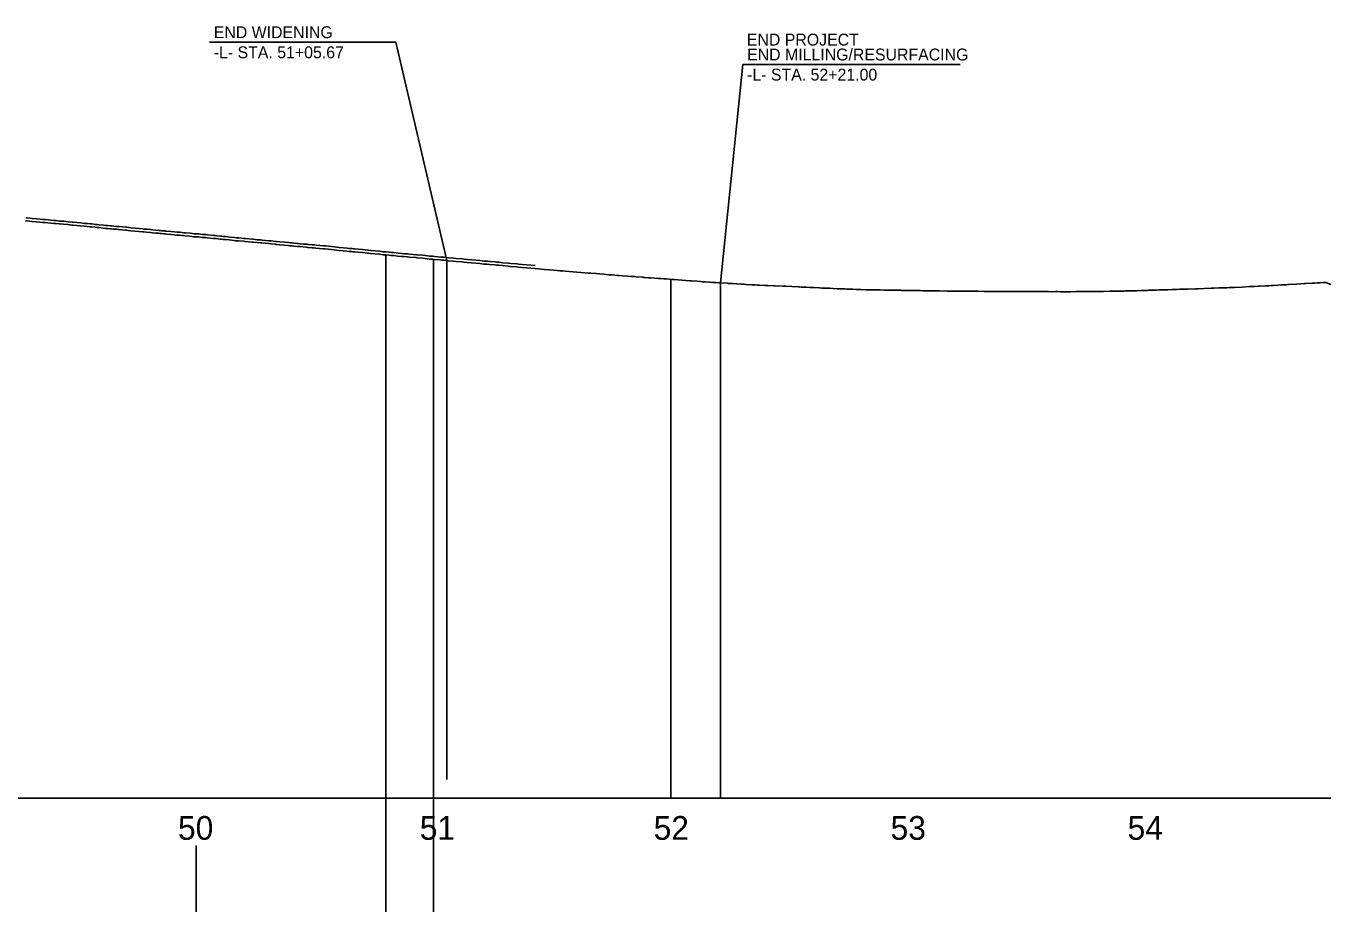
# Model space of a CAD drawing. Extents: x 2115752 to 2121174, y 562881 to 567245.
# Drawn here: x 2120625 to 2121174, y 566328 to 566701 of the extents above; entities that cross this region are included whole.
import ezdxf

# ---------------------------------------------------------------- set-up
doc = ezdxf.new("R2010")
doc.units = 0
for name, color, linetype in [('Exist Profile Cell', 7, 'Continuous'), ('Exist Vertical Profile Ground Line', 7, 'Continuous'), ('Exist Vertical Profile Horizontal Axis Label Major', 7, 'Continuous'), ('Prop VPI Label', 7, 'Continuous'), ('Scratch_Level_1', 7, 'Continuous')]:
    doc.layers.add(name, color=color, linetype=linetype)

msp = doc.modelspace()

# ---------------------------------------------------------------- linework, layer by layer
at = {"layer": 'Exist Profile Cell'}
msp.add_line((2116696.3, 566375.81), (2121174.42, 566375.81), dxfattribs=at)
at = {"layer": 'Exist Vertical Profile Ground Line'}
for points in [[(2120624.5, 566618.97), (2120625.07, 566618.92), (2120626.09, 566618.8), (2120627.11, 566618.72), (2120628.94, 566618.55), (2120630.45, 566618.41), (2120631.56, 566618.27), (2120632.57, 566618.21), (2120633.82, 566618.09), (2120635.04, 566617.95), (2120636.31, 566617.88), (2120636.7, 566617.85), (2120637.16, 566617.81), (2120638.57, 566617.63), (2120640.46, 566617.5), (2120642.26, 566617.34), (2120643.96, 566617.19), (2120644.45, 566617.14), (2120647.64, 566616.84), (2120649.14, 566616.64), (2120650.48, 566616.53), (2120651.62, 566616.44), (2120652.2, 566616.38), (2120653.77, 566616.23), (2120654.57, 566616.13), (2120655.3, 566616.09), (2120657.16, 566615.91), (2120658.08, 566615.79), (2120658.97, 566615.73), (2120659.96, 566615.63), (2120660.52, 566615.58), (2120661.58, 566615.45), (2120662.71, 566615.39), (2120663.3, 566615.33), (2120663.81, 566615.29), (2120666.62, 566615.03), (2120667.16, 566614.98), (2120667.71, 566614.9), (2120668.75, 566614.76), (2120670.55, 566614.64), (2120672.22, 566614.43), (2120673.77, 566614.32), (2120674.36, 566614.26), (2120675.47, 566614.16), (2120677.14, 566614.01), (2120678.01, 566613.93), (2120679.28, 566613.76), (2120680.44, 566613.69), (2120681.12, 566613.62), (2120681.8, 566613.56), (2120682.82, 566613.44), (2120683.22, 566613.41), (2120683.77, 566613.37), (2120685.62, 566613.21), (2120687.04, 566613.08), (2120688.2, 566612.95), (2120689.35, 566612.88), (2120690.35, 566612.78), (2120690.98, 566612.71), (2120691.71, 566612.62), (2120693.7, 566612.49), (2120695.33, 566612.28), (2120697.26, 566612.17)], [(2120697.26, 566612.17), (2120698.82, 566611.97), (2120700.43, 566611.89), (2120700.98, 566611.83), (2120703.66, 566611.56), (2120704.18, 566611.51), (2120704.76, 566611.45), (2120706.48, 566611.28), (2120706.98, 566611.23), (2120707.69, 566611.16), (2120708.62, 566611.05), (2120710.26, 566610.9), (2120712.33, 566610.7), (2120713.05, 566610.59), (2120713.62, 566610.56), (2120714.24, 566610.5), (2120716.31, 566610.32), (2120716.94, 566610.26), (2120719.99, 566610), (2120720.29, 566609.97), (2120721.99, 566609.77), (2120723.49, 566609.67), (2120724.02, 566609.62), (2120726.78, 566609.36), (2120727.75, 566609.26), (2120729.75, 566609.06), (2120730.08, 566609.02), (2120731.52, 566608.88), (2120733.41, 566608.71), (2120735.16, 566608.54), (2120736, 566608.43), (2120736.72, 566608.39), (2120737.5, 566608.32), (2120739.03, 566608.18), (2120740.02, 566608.08), (2120741.41, 566607.94), (2120743.01, 566607.81), (2120743.43, 566607.77), (2120745.25, 566607.6), (2120746.01, 566607.53), (2120746.73, 566607.46), (2120749.87, 566607.2), (2120750.23, 566607.17), (2120750.66, 566607.12), (2120753.23, 566606.83), (2120754.46, 566606.71), (2120756.49, 566606.51), (2120758.24, 566606.34), (2120759.78, 566606.19), (2120760.76, 566606.1), (2120761.96, 566606), (2120762.5, 566605.93), (2120762.99, 566605.89), (2120764.49, 566605.72), (2120766.36, 566605.59), (2120768.52, 566605.38), (2120768.89, 566605.34), (2120769.82, 566605.25), (2120773.53, 566604.9), (2120775.07, 566604.7), (2120776.27, 566604.63), (2120777.58, 566604.51), (2120778.56, 566604.38), (2120779.53, 566604.31), (2120781.32, 566604.14), (2120782.79, 566604), (2120784.03, 566603.87), (2120785.31, 566603.77), (2120786.14, 566603.7), (2120789.01, 566603.46), (2120789.44, 566603.41), (2120791.78, 566603.2), (2120792.78, 566603.11), (2120794.54, 566602.88), (2120795.91, 566602.8), (2120796.78, 566602.71), (2120799.27, 566602.47), (2120799.9, 566602.41), (2120800.65, 566602.35), (2120802.52, 566602.16), (2120804.58, 566601.97), (2120805.84, 566601.86), (2120808.34, 566601.67), (2120809.1, 566601.6), (2120810.52, 566601.42), (2120812.38, 566601.3), (2120815.9, 566600.97), (2120817.58, 566600.77), (2120818.93, 566600.67), (2120820.07, 566600.56), (2120822.16, 566600.37), (2120822.91, 566600.3), (2120823.87, 566600.23), (2120825.47, 566600.08), (2120827.75, 566599.88), (2120828.76, 566599.79), (2120831.37, 566599.55), (2120832.04, 566599.49), (2120833.58, 566599.33), (2120835.5, 566599.2), (2120839.1, 566598.88)], [(2120839.1, 566598.88), (2120840.75, 566598.7), (2120841.83, 566598.63), (2120843.1, 566598.52), (2120845.16, 566598.33), (2120847.02, 566598.17), (2120848.41, 566598.06), (2120849.51, 566597.94), (2120850.89, 566597.86), (2120851.78, 566597.78), (2120855.04, 566597.42), (2120858.41, 566597.23), (2120860.12, 566597.08), (2120861.51, 566596.98), (2120862.01, 566596.94), (2120862.55, 566596.89), (2120864.84, 566596.72), (2120866.26, 566596.6), (2120868.15, 566596.44), (2120869.12, 566596.36), (2120870.26, 566596.26), (2120871.4, 566596.16), (2120873.93, 566595.95), (2120874.66, 566595.89), (2120876.08, 566595.78), (2120878, 566595.62), (2120879.66, 566595.53), (2120881.21, 566595.45), (2120881.67, 566595.41), (2120884.53, 566595.19), (2120884.96, 566595.16), (2120885.57, 566595.11), (2120886.87, 566595), (2120887.75, 566594.94), (2120889.42, 566594.82), (2120891.05, 566594.72), (2120892.06, 566594.67), (2120893.33, 566594.56), (2120894.37, 566594.49), (2120896.98, 566594.31), (2120897.67, 566594.26), (2120899.23, 566594.14), (2120900.99, 566593.96), (2120902.64, 566593.85), (2120904.13, 566593.74), (2120904.55, 566593.71), (2120905.02, 566593.67), (2120907.46, 566593.5), (2120908.79, 566593.4), (2120909.81, 566593.31), (2120910.72, 566593.27), (2120912.65, 566593.13), (2120914.02, 566593.04), (2120915.16, 566592.98), (2120916.56, 566592.88), (2120916.95, 566592.85), (2120917.29, 566592.83), (2120920.19, 566592.64), (2120920.64, 566592.61), (2120922.27, 566592.5), (2120924.1, 566592.4), (2120925.79, 566592.3), (2120927.24, 566592.24), (2120928.1, 566592.2), (2120930.4, 566592.07), (2120931.1, 566592.05), (2120931.9, 566591.98), (2120932.9, 566591.9), (2120933.74, 566591.88), (2120935.92, 566591.78), (2120936.5, 566591.74), (2120937.02, 566591.72), (2120939.65, 566591.59), (2120940.3, 566591.56), (2120943.63, 566591.43), (2120944.61, 566591.4), (2120947.31, 566591.33), (2120950.17, 566591.14), (2120950.6, 566591.09), (2120951.17, 566591.06), (2120953.41, 566590.96), (2120955.02, 566590.89), (2120956.74, 566590.81), (2120958.9, 566590.69), (2120959.9, 566590.62), (2120961.2, 566590.55), (2120962.77, 566590.55), (2120963.26, 566590.53), (2120964.75, 566590.43), (2120966.57, 566590.32), (2120968.37, 566590.28), (2120969.82, 566590.26), (2120970.52, 566590.24), (2120971.87, 566590.17), (2120973.07, 566590.15), (2120974.42, 566590.1), (2120976.37, 566590.03), (2120978.3, 566589.96), (2120979.67, 566589.92), (2120982.08, 566589.86), (2120982.89, 566589.84)], [(2120982.89, 566589.84), (2120984.3, 566589.83), (2120986.26, 566589.82), (2120987.99, 566589.8), (2120989.85, 566589.77), (2120992.79, 566589.7), (2120993.17, 566589.69), (2120993.61, 566589.68), (2120994.97, 566589.62), (2120996.08, 566589.65), (2120997.61, 566589.62), (2120999.33, 566589.59), (2121001.36, 566589.57), (2121002.58, 566589.52), (2121005.2, 566589.52), (2121005.93, 566589.5), (2121009.4, 566589.46), (2121012.88, 566589.39), (2121014.42, 566589.33), (2121015.7, 566589.34), (2121016.95, 566589.32), (2121018.92, 566589.27), (2121020.77, 566589.27), (2121022.32, 566589.27), (2121024.59, 566589.29), (2121025.53, 566589.29), (2121028.36, 566589.25), (2121028.79, 566589.24), (2121030.41, 566589.17), (2121032.06, 566589.21), (2121032.38, 566589.21), (2121035.36, 566589.2), (2121036.19, 566589.2), (2121038.68, 566589.17), (2121039.32, 566589.15), (2121040.02, 566589.16), (2121041.95, 566589.16), (2121042.81, 566589.14), (2121043.81, 566589.16), (2121044.57, 566589.15), (2121045.22, 566589.15), (2121047.79, 566589.16), (2121048.15, 566589.16), (2121048.5, 566589.16), (2121051.91, 566589.16), (2121055.14, 566589.16), (2121055.51, 566589.16), (2121056.97, 566589.12), (2121058.36, 566589.13), (2121059.37, 566589.13), (2121060.52, 566589.1), (2121061.58, 566589.12), (2121063.21, 566589.12), (2121064.91, 566589.12), (2121067.1, 566589.15), (2121068.22, 566589.15), (2121070.96, 566589.18), (2121071.51, 566589.18), (2121074.77, 566589.23), (2121078.02, 566589.25), (2121078.57, 566589.26), (2121081.29, 566589.3), (2121082.45, 566589.33), (2121084.57, 566589.37), (2121085.38, 566589.37), (2121086.39, 566589.4), (2121087.21, 566589.4), (2121087.9, 566589.43), (2121090.18, 566589.48), (2121091.2, 566589.5), (2121092.57, 566589.53), (2121094.46, 566589.6), (2121097.01, 566589.68), (2121097.75, 566589.71), (2121099.56, 566589.74), (2121100.94, 566589.81), (2121101.86, 566589.84), (2121104.2, 566589.91), (2121105.65, 566589.95), (2121107.52, 566590), (2121108.43, 566590.02), (2121109.54, 566590.08), (2121110.8, 566590.11), (2121111.95, 566590.11), (2121113.44, 566590.19), (2121114.08, 566590.21), (2121117.36, 566590.32), (2121118.49, 566590.36), (2121121.04, 566590.44), (2121123.99, 566590.54), (2121124.43, 566590.55), (2121124.92, 566590.58), (2121127.19, 566590.67), (2121127.92, 566590.69), (2121128.75, 566590.73), (2121130.51, 566590.8), (2121131.51, 566590.83), (2121132.7, 566590.89), (2121133.31, 566590.9), (2121133.85, 566590.93), (2121137.04, 566591.07)], [(2121137.04, 566591.07), (2121140.03, 566591.23), (2121140.43, 566591.25), (2121142.12, 566591.29), (2121143.94, 566591.42), (2121144.29, 566591.44), (2121146.88, 566591.58), (2121147.45, 566591.61), (2121148.12, 566591.65), (2121149.26, 566591.68), (2121150.18, 566591.75), (2121152.03, 566591.86), (2121153.45, 566591.94), (2121155.77, 566592.07), (2121156.31, 566592.09), (2121156.76, 566592.13), (2121159.99, 566592.32), (2121161.6, 566592.38), (2121163.25, 566592.51), (2121163.67, 566592.53), (2121166.59, 566592.71), (2121167.51, 566592.77), (2121168.77, 566592.81), (2121169.79, 566592.89), (2121171.3, 566592.98), (2121172.29, 566593), (2121172.63, 566592.81), (2121174.42, 566592.08)]]:
    msp.add_lwpolyline(points, dxfattribs=at)
at = {"layer": 'Prop VPI Label'}
for p, q in [((2120701.97, 566694.12), (2120780.53, 566694.12)), ((2120801.97, 566602.21), (2120780.53, 566694.12)), ((2120917.3, 566592.83), (2120926.69, 566684.74)), ((2120926.69, 566684.74), (2121018.26, 566684.74))]:
    msp.add_line(p, q, dxfattribs=at)
at = {"layer": 'Scratch_Level_1'}
for p, q in [((2120776.3, 566327.95), (2120776.3, 566604.62)), ((2120796.3, 566327.95), (2120796.3, 566602.79)), ((2120801.97, 566383.73), (2120801.97, 566602.21)), ((2120896.3, 566375.81), (2120896.3, 566594.29)), ((2120917.3, 566375.81), (2120917.3, 566592.83)), ((2120696.3, 566327.95), (2120696.3, 566355.91))]:
    msp.add_line(p, q, dxfattribs=at)
for points in [[(2120624.61, 566620.21), (2120625.2, 566620.17), (2120626.21, 566620.04), (2120627.21, 566619.96), (2120629.06, 566619.8), (2120630.58, 566619.65), (2120631.67, 566619.52), (2120632.67, 566619.46), (2120633.96, 566619.33), (2120635.14, 566619.19), (2120636.4, 566619.13), (2120636.81, 566619.09), (2120637.29, 566619.05), (2120638.69, 566618.87), (2120640.55, 566618.75), (2120642.37, 566618.59), (2120644.07, 566618.43), (2120644.57, 566618.39), (2120647.78, 566618.08), (2120649.27, 566617.88), (2120650.58, 566617.78), (2120651.73, 566617.68), (2120652.32, 566617.63), (2120653.91, 566617.47), (2120654.68, 566617.37), (2120655.39, 566617.33), (2120657.3, 566617.15), (2120658.2, 566617.04), (2120659.07, 566616.98), (2120660.08, 566616.88), (2120660.66, 566616.82), (2120661.69, 566616.7), (2120662.8, 566616.63), (2120663.42, 566616.58), (2120663.92, 566616.53), (2120666.74, 566616.27), (2120667.31, 566616.22), (2120667.88, 566616.14), (2120668.88, 566616), (2120670.68, 566615.89), (2120672.35, 566615.67), (2120673.88, 566615.57), (2120674.48, 566615.51), (2120675.58, 566615.41), (2120677.26, 566615.25), (2120678.15, 566615.17), (2120679.4, 566615.01), (2120680.54, 566614.94), (2120681.23, 566614.86), (2120681.92, 566614.81), (2120682.94, 566614.68), (2120683.3, 566614.66), (2120683.86, 566614.62), (2120685.73, 566614.46), (2120687.17, 566614.33), (2120688.3, 566614.2), (2120689.45, 566614.13), (2120690.48, 566614.03), (2120691.13, 566613.95), (2120691.82, 566613.86), (2120693.82, 566613.74), (2120695.45, 566613.53), (2120697.33, 566613.42)], [(2120697.43, 566613.41), (2120698.93, 566613.22), (2120700.52, 566613.13), (2120701.1, 566613.08), (2120703.78, 566612.8), (2120704.31, 566612.75), (2120704.89, 566612.69), (2120706.61, 566612.52), (2120707.1, 566612.47), (2120707.82, 566612.4), (2120708.75, 566612.3), (2120710.38, 566612.14), (2120712.48, 566611.94), (2120713.18, 566611.84), (2120713.72, 566611.8), (2120714.35, 566611.75), (2120716.42, 566611.56), (2120717.05, 566611.5), (2120720.1, 566611.24), (2120720.42, 566611.21), (2120722.1, 566611.02), (2120723.59, 566610.92), (2120724.14, 566610.87), (2120726.9, 566610.6), (2120727.87, 566610.5), (2120729.87, 566610.3), (2120730.2, 566610.27), (2120731.64, 566610.13), (2120733.52, 566609.95), (2120735.3, 566609.79), (2120736.12, 566609.67), (2120736.81, 566609.63), (2120737.61, 566609.56), (2120739.15, 566609.42), (2120740.15, 566609.32), (2120741.52, 566609.18), (2120743.13, 566609.06), (2120743.55, 566609.01), (2120745.37, 566608.85), (2120746.13, 566608.78), (2120746.84, 566608.71), (2120749.97, 566608.45), (2120750.35, 566608.42), (2120750.8, 566608.36), (2120753.36, 566608.08), (2120754.59, 566607.96), (2120756.61, 566607.75), (2120758.36, 566607.59), (2120759.9, 566607.44), (2120760.87, 566607.35), (2120762.09, 566607.24), (2120762.62, 566607.17), (2120763.11, 566607.14), (2120764.6, 566606.97), (2120766.47, 566606.83), (2120768.64, 566606.62), (2120769.01, 566606.59), (2120769.94, 566606.49), (2120773.67, 566606.15), (2120775.19, 566605.94), (2120776.37, 566605.87), (2120777.72, 566605.75), (2120778.69, 566605.63), (2120779.64, 566605.56), (2120781.44, 566605.39), (2120782.92, 566605.24), (2120784.14, 566605.11), (2120785.41, 566605.02), (2120786.25, 566604.94), (2120789.13, 566604.7), (2120789.55, 566604.66), (2120791.89, 566604.45), (2120792.91, 566604.35), (2120794.66, 566604.13), (2120796.01, 566604.04), (2120796.9, 566603.96), (2120799.39, 566603.72), (2120800.01, 566603.65), (2120800.76, 566603.59), (2120802.64, 566603.4), (2120804.69, 566603.22), (2120805.95, 566603.1), (2120808.45, 566602.91), (2120809.23, 566602.84), (2120810.63, 566602.67), (2120812.47, 566602.55), (2120816.03, 566602.22), (2120817.7, 566602.01), (2120819.04, 566601.91), (2120820.19, 566601.81), (2120822.28, 566601.62), (2120823.01, 566601.54), (2120823.97, 566601.48), (2120825.58, 566601.32), (2120827.86, 566601.12), (2120828.87, 566601.03), (2120831.48, 566600.8), (2120832.16, 566600.74), (2120833.69, 566600.58), (2120835.59, 566600.45), (2120839.22, 566600.12)]]:
    msp.add_lwpolyline(points, dxfattribs=at)

# ---------------------------------------------------------------- texts
at = {"layer": 'Exist Vertical Profile Horizontal Axis Label Major'}
for s, p in [('50', (2120688.69, 566358.31)), ('51', (2120790.53, 566358.31)), ('52', (2120889.08, 566358.31)), ('53', (2120988.91, 566358.31)), ('54', (2121088.76, 566358.31))]:
    msp.add_text(s, height=10, dxfattribs=at).set_placement(p)
at = {"layer": 'Prop VPI Label'}
for s, p in [('END WIDENING', (2120703.75, 566695.88)), ('-L- STA. 51+05.67', (2120703.75, 566687.42)), ('END PROJECT', (2120928.35, 566692.76)), ('END MILLING/RESURFACING', (2120928.46, 566686.49)), ('-L- STA. 52+21.00', (2120928.46, 566678.03))]:
    msp.add_text(s, height=5, dxfattribs=at).set_placement(p)

doc.saveas('drawing.dxf')
